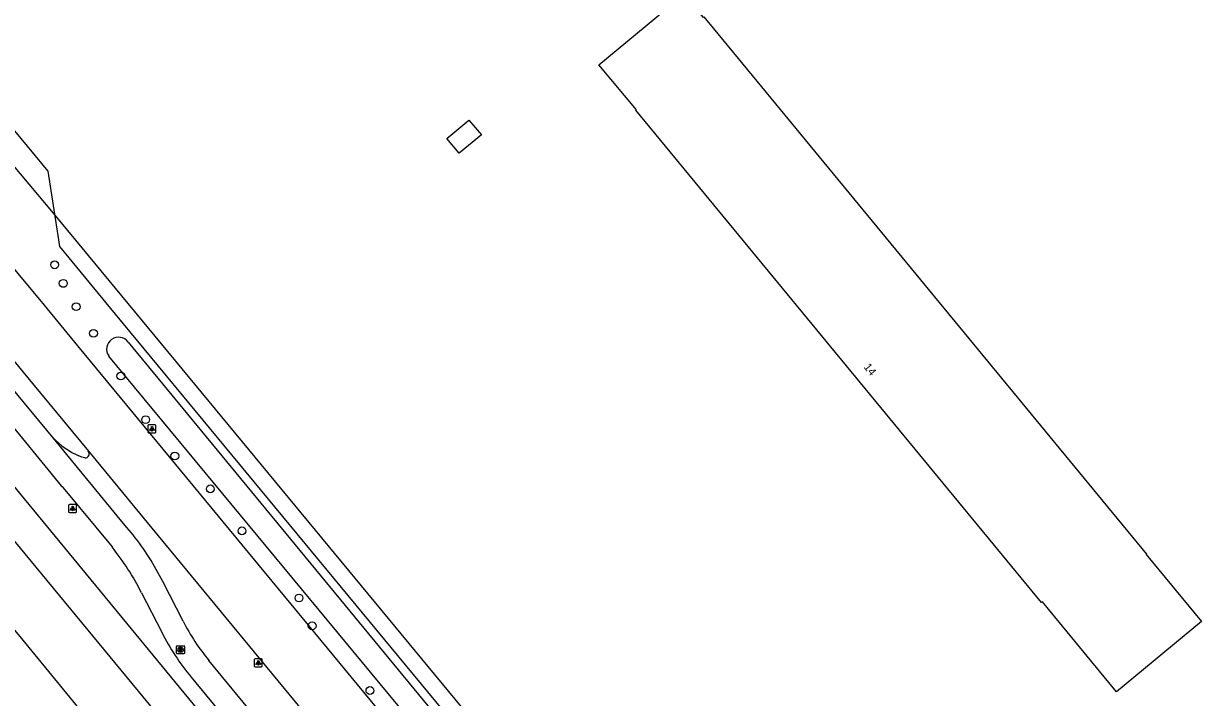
# Model space of a CAD drawing. Extents: x 156141 to 158132, y 385651 to 388399.
# Drawn here: x 157143.7 to 157290.9, y 387004.8 to 387089 of the extents above; entities that cross this region are included whole.
import ezdxf

# ---------------------------------------------------------------- set-up
doc = ezdxf.new("R2010")
doc.units = 0
for name, color, linetype in [('IMGEO_Berm_gesloten', 7, 'Continuous'), ('IMGEO_Berm_groen', 7, 'Continuous'), ('IMGEO_Boom', 7, 'Continuous'), ('IMGEO_Fietspad_gesloten', 7, 'Continuous'), ('IMGEO_Hek', 7, 'Continuous'), ('IMGEO_Lichtpunt', 7, 'Continuous'), ('IMGEO_Pand', 7, 'Continuous'), ('IMGEO_Pand_nummerreeks', 7, 'Continuous'), ('IMGEO_Rijbaan_lokaal_gesloten', 7, 'Continuous'), ('IMGEO_Rijbaan_lokaal_open', 7, 'Continuous'), ('IMGEO_Rioolput', 7, 'Continuous'), ('IMGEO_Waterloop', 7, 'Continuous')]:
    doc.layers.add(name, color=color, linetype=linetype)

msp = doc.modelspace()

# ---------------------------------------------------------------- linework, layer by layer
at = {"layer": 'IMGEO_Berm_gesloten'}
msp.add_lwpolyline([(157151.38, 387034.77), (157151.01, 387034.86), (157150.64, 387035.01)], dxfattribs=at)
for centre, radius, start, end in [((157154.98, 387044.64), 10.56, 224.1914, 245.7485), ((157151.41, 387035.29), 0.519, 266.4563, 39.0103)]:
    msp.add_arc(centre, radius, start, end, dxfattribs=at)
at = {"layer": 'IMGEO_Berm_groen'}
for points in [[(157241.17, 386912.07), (157168.24, 387000), (157137.21, 387037.65), (157129.35, 387046.65), (157129.18, 387046.53), (157127.01, 387049.14), (157127.14, 387049.25), (157124.86, 387052.05), (157124.73, 387051.94), (157091.86, 387091.79), (157084.85, 387100.37), (157072.38, 387115.63), (157065.43, 387124.28), (157056.49, 387135.39)], [(157137.84, 387076.72), (157147.62, 387065.08), (157205.96, 386994.56)]]:
    msp.add_lwpolyline(points, dxfattribs=at)
at = {"layer": 'IMGEO_Boom'}
for centre in [(157147.61, 387058.9), (157148.68, 387056.57), (157150.29, 387053.66), (157152.46, 387050.34), (157155.87, 387045), (157158.98, 387039.54), (157162.62, 387035), (157167.07, 387030.9), (157171.02, 387025.65), (157178.15, 387017.27), (157179.79, 387013.78), (157187.01, 387005.7)]:
    msp.add_circle(centre, 0.489, dxfattribs=at)
at = {"layer": 'IMGEO_Fietspad_gesloten'}
for points in [[(157073.27, 387122.58), (157074.48, 387121.12), (157080.02, 387114.42), (157086.19, 387106.9), (157095.11, 387096.08), (157108.21, 387080.17), (157121.46, 387064.05), (157133.33, 387049.65), (157140.75, 387040.62), (157148.43, 387031.28), (157148.54, 387031.18), (157148.69, 387031.02), (157154.78, 387023.64)], [(157147.4, 387037.28), (157143.06, 387042.56), (157115.71, 387075.82)], [(157157.41, 387025.14), (157156.38, 387026.35), (157147.4, 387037.28)], [(157163.67, 387014.36), (157161.12, 387019.32)], [(157158.45, 387017.92), (157161, 387012.98)], [(157190.16, 386981.21), (157174.68, 387000), (157166.89, 387009.45)], [(157164.67, 387007.38), (157170.76, 387000), (157242.5, 386913.02)]]:
    msp.add_lwpolyline(points, dxfattribs=at)
for centre, radius, start, end in [((157131.1, 387004.26), 33.59, 26.6363, 38.4271), ((157129, 387003.03), 33.01, 26.8098, 38.6353), ((157187.72, 387026.66), 27.02, 207.0669, 219.5562), ((157186.97, 387026.02), 29.06, 206.6505, 219.885)]:
    msp.add_arc(centre, radius, start, end, dxfattribs=at)
at = {"layer": 'IMGEO_Hek'}
for points in [[(157133.43, 387086.67), (157146.77, 387070.58), (157148, 387062.56)], [(157148, 387062.56), (157148.22, 387061.17)], [(157148.22, 387061.17), (157155.18, 387052.74)], [(157155.18, 387052.74), (157198.78, 387000)]]:
    msp.add_lwpolyline(points, dxfattribs=at)
at = {"layer": 'IMGEO_Lichtpunt'}
for p, q in [((157159.26, 387038.81), (157159.26, 387038)), ((157159.26, 387038.81), (157159.26, 387038)), ((157160.16, 387038.91), (157159.35, 387038.91)), ((157160.16, 387038.91), (157159.35, 387038.91)), ((157159.35, 387037.91), (157160.16, 387037.91)), ((157159.35, 387037.91), (157160.16, 387037.91)), ((157160.25, 387038), (157160.25, 387038.81)), ((157160.25, 387038), (157160.25, 387038.81)), ((157149.35, 387028.84), (157149.35, 387028.04)), ((157149.35, 387028.84), (157149.35, 387028.04)), ((157150.25, 387028.94), (157149.45, 387028.94)), ((157150.25, 387028.94), (157149.45, 387028.94)), ((157149.45, 387027.94), (157150.25, 387027.94)), ((157149.45, 387027.94), (157150.25, 387027.94)), ((157150.35, 387028.04), (157150.35, 387028.84)), ((157150.35, 387028.04), (157150.35, 387028.84)), ((157172.56, 387009.57), (157172.56, 387008.76)), ((157172.56, 387009.57), (157172.56, 387008.76)), ((157173.46, 387009.66), (157172.65, 387009.66)), ((157173.46, 387009.66), (157172.65, 387009.66)), ((157172.65, 387008.66), (157173.46, 387008.66)), ((157172.65, 387008.66), (157173.46, 387008.66)), ((157173.55, 387008.76), (157173.55, 387009.57)), ((157173.55, 387008.76), (157173.55, 387009.57))]:
    msp.add_line(p, q, dxfattribs=at)
for points in [[(157159.63, 387038.47), (157159.67, 387038.45), (157159.48, 387038.18), (157159.44, 387038.21), (157159.63, 387038.47)], [(157159.73, 387038.43), (157159.78, 387038.43), (157159.78, 387038.1), (157159.73, 387038.1), (157159.73, 387038.43)], [(157159.84, 387038.45), (157159.88, 387038.47), (157160.07, 387038.21), (157160.03, 387038.18), (157159.84, 387038.45)], [(157149.73, 387028.51), (157149.76, 387028.48), (157149.58, 387028.22), (157149.54, 387028.24), (157149.73, 387028.51)], [(157149.83, 387028.46), (157149.88, 387028.46), (157149.88, 387028.14), (157149.83, 387028.14), (157149.83, 387028.46)], [(157149.94, 387028.48), (157149.98, 387028.51), (157150.16, 387028.24), (157150.12, 387028.22), (157149.94, 387028.48)], [(157172.93, 387009.23), (157172.97, 387009.2), (157172.78, 387008.94), (157172.74, 387008.97), (157172.93, 387009.23)], [(157173.03, 387009.18), (157173.08, 387009.18), (157173.08, 387008.86), (157173.03, 387008.86), (157173.03, 387009.18)], [(157173.14, 387009.2), (157173.18, 387009.23), (157173.37, 387008.97), (157173.33, 387008.94), (157173.14, 387009.2)]]:
    msp.add_lwpolyline(points, dxfattribs=at)
for centre in [(157159.76, 387038.61), (157149.85, 387028.64), (157173.06, 387009.36)]:
    msp.add_circle(centre, 0.0994, dxfattribs=at)
for centre, start, end in [((157159.35, 387038.81), 90, 180), ((157159.35, 387038.81), 90, 180), ((157159.35, 387038), 180, 270), ((157159.35, 387038), 180, 270), ((157160.16, 387038.81), 0, 90), ((157160.16, 387038.81), 0, 90), ((157160.16, 387038), 270, 0), ((157160.16, 387038), 270, 360), ((157149.45, 387028.84), 90, 180), ((157149.45, 387028.84), 90, 180), ((157149.45, 387028.04), 180, 270), ((157149.45, 387028.04), 180, 270), ((157150.25, 387028.84), 0, 90), ((157150.25, 387028.84), 0, 90), ((157150.25, 387028.04), 270, 0), ((157150.25, 387028.04), 270, 360), ((157172.65, 387009.57), 90, 180), ((157172.65, 387009.57), 90, 180), ((157172.65, 387008.76), 180, 270), ((157172.65, 387008.76), 180, 270), ((157173.46, 387009.57), 0, 90), ((157173.46, 387009.57), 0, 90), ((157173.46, 387008.76), 270, 0), ((157173.46, 387008.76), 270, 360)]:
    msp.add_arc(centre, 0.0946, start, end, dxfattribs=at)
at = {"layer": 'IMGEO_Pand'}
for points in [[(157284.07, 387022.73), (157284.01, 387022.68), (157290.93, 387014.33), (157280.32, 387005.53), (157271.05, 387016.78), (157270.95, 387016.71), (157220.25, 387078.2), (157220.31, 387078.25), (157215.63, 387083.89), (157226.26, 387092.72), (157228.64, 387089.8), (157228.72, 387089.86), (157284.07, 387022.73)], [(157200.94, 387075.14), (157198.16, 387072.83), (157196.61, 387074.67), (157199.39, 387076.98), (157200.94, 387075.14)]]:
    msp.add_lwpolyline(points, dxfattribs=at)
at = {"layer": 'IMGEO_Rijbaan_lokaal_gesloten'}
for points in [[(157117.1, 387077.69), (157144.85, 387044.06), (157151.82, 387035.62)], [(157135.44, 387066.9), (157136.6, 387065.48), (157146.3, 387053.84), (157150.47, 387048.79), (157190.74, 387000), (157199.69, 386989.11)], [(157151.82, 387035.62), (157159.75, 387026), (157181.21, 387000), (157194.91, 386983.4)]]:
    msp.add_lwpolyline(points, dxfattribs=at)
at = {"layer": 'IMGEO_Rijbaan_lokaal_open'}
for points in [[(157160.83, 386861.48), (157229.85, 386918.64), (157081.95, 387097.87), (157078.51, 387102.05)], [(157214.97, 386925.48), (157169.44, 386980.52), (157143.68, 387011.99), (157121.58, 387038.54), (157110.85, 387029.54)]]:
    msp.add_lwpolyline(points, dxfattribs=at)
at = {"layer": 'IMGEO_Rioolput'}
for p, q in [((157162.84, 387010.37), (157162.84, 387011.22)), ((157162.92, 387011.29), (157163.77, 387011.29)), ((157163.77, 387010.29), (157162.92, 387010.29)), ((157163.33, 387011.07), (157163.35, 387011.07)), ((157163.35, 387010.51), (157163.33, 387010.51)), ((157163.84, 387011.22), (157163.84, 387010.37))]:
    msp.add_line(p, q, dxfattribs=at)
for points in [[(157162.84, 387010.37), (157162.84, 387011.22)], [(157162.92, 387011.29), (157163.77, 387011.29)], [(157163.77, 387010.29), (157162.92, 387010.29)], [(157163.43, 387010.99), (157163.18, 387010.99), (157163.18, 387010.59)], [(157163.18, 387010.59), (157163.3, 387010.59), (157163.3, 387010.76), (157163.31, 387010.76)], [(157163.36, 387010.91), (157163.3, 387010.91), (157163.3, 387010.83)], [(157163.3, 387010.83), (157163.35, 387010.83)], [(157163.36, 387010.73), (157163.43, 387010.59), (157163.57, 387010.59), (157163.51, 387010.72)], [(157163.84, 387011.22), (157163.84, 387010.37)]]:
    msp.add_lwpolyline(points, dxfattribs=at)
for centre, radius, start, end in [((157162.92, 387011.22), 0.0765, 91.552, 178.448), ((157162.92, 387011.22), 0.0765, 91.552, 178.448), ((157162.92, 387010.37), 0.0765, 181.552, 268.448), ((157162.92, 387010.37), 0.0765, 181.552, 268.448), ((157163.31, 387010.7), 0.0533, 26.0293, 88.6989), ((157163.34, 387011.02), 0.19, 274.7715, 282.9687), ((157163.36, 387010.82), 0.0964, 77.0061, 93.1865), ((157163.38, 387010.87), 0.0378, 276.6634, 79.6772), ((157163.43, 387010.88), 0.109, 350.3612, 89.416), ((157163.43, 387010.88), 0.112, 277.5842, 350.9817), ((157163.41, 387010.67), 0.108, 29.5134, 73.7905), ((157163.77, 387011.22), 0.0765, 1.552, 88.448), ((157163.77, 387011.22), 0.0765, 1.552, 88.448), ((157163.77, 387010.37), 0.0765, 271.552, 358.448), ((157163.77, 387010.37), 0.0765, 271.552, 358.448)]:
    msp.add_arc(centre, radius, start, end, dxfattribs=at)
for centre, major_axis, ratio, start_param, end_param in [((157163.33, 387010.79), (-0.387, 0.002), 0.722429, 4.712389, 7.853982), ((157163.35, 387010.79), (-0.39, 0.002), 0.717154, 1.570796, 4.712389)]:
    msp.add_ellipse(centre, major_axis=major_axis, ratio=ratio, start_param=start_param, end_param=end_param, dxfattribs=at)
at = {"layer": 'IMGEO_Waterloop'}
for points in [[(157156.81, 387049.25), (157197.37, 387000), (157202.32, 386994.04)], [(157200.18, 386992.19), (157193.72, 387000), (157154.36, 387047.5)]]:
    msp.add_lwpolyline(points, dxfattribs=at)
msp.add_arc((157155.6, 387048.35), 1.5, 36.825, 214.454, dxfattribs=at)

# ---------------------------------------------------------------- texts
at = {"layer": 'IMGEO_Pand_nummerreeks'}
msp.add_text('14', height=1, rotation=309.5052, dxfattribs=at).set_placement((157248.67, 387046.09))

doc.saveas('drawing.dxf')
